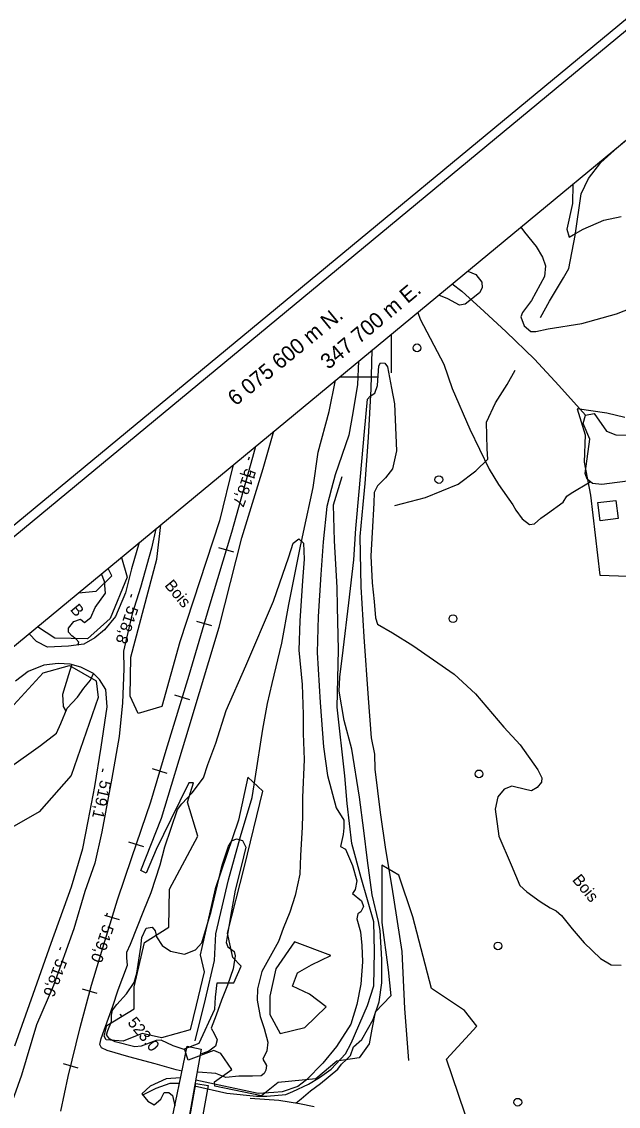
# Model space of a CAD drawing. Extents: x 347312 to 350503, y 6073086 to 6076432.
# Drawn here: x 347604 to 347759, y 6075410.5 to 6075692.2 of the extents above; entities that cross this region are included whole.
import ezdxf

# ---------------------------------------------------------------- set-up
doc = ezdxf.new("R2010")
doc.units = 0
for name, color, linetype in [('Level 1', 7, 'Continuous'), ('Level 19', 7, 'Continuous'), ('Level 2', 7, 'Continuous'), ('Level 22', 7, 'Continuous'), ('Level 23', 7, 'Continuous'), ('Level 26', 7, 'Continuous'), ('Level 3', 7, 'Continuous'), ('Level 31', 7, 'Continuous'), ('Level 36', 7, 'Continuous'), ('Level 4', 7, 'Continuous'), ('Level 44', 7, 'Continuous'), ('Level 54', 7, 'Continuous'), ('Level 60', 7, 'Continuous'), ('Level 61', 7, 'Continuous')]:
    doc.layers.add(name, color=color, linetype=linetype)

msp = doc.modelspace()

# ---------------------------------------------------------------- linework, layer by layer
at = {"layer": 'Level 1'}
for points in [[(347652.33, 6075499.3), (347654.48, 6075504.82), (347657.14, 6075513.31), (347662.23, 6075524.88), (347669.46, 6075541.69), (347673.43, 6075553.21), (347674.57, 6075556.8), (347676.01, 6075557.93), (347677.25, 6075556.76), (347677.37, 6075552.62), (347676.98, 6075547), (347676.29, 6075536.62), (347676, 6075529.02), (347676.85, 6075520.07), (347677.13, 6075512.28), (347677.18, 6075507.36), (347677.42, 6075500.6), (347676.99, 6075490.74), (347676.94, 6075486.27)], [(347616.15, 6075534.73), (347617.57, 6075536.43), (347619.25, 6075537.02), (347620.35, 6075536.19), (347621.95, 6075537.51), (347623.08, 6075540.05), (347625.8, 6075543.77), (347625.8, 6075543.77), (347625.49, 6075546.84), (347624.73, 6075548.8)], [(347618.61, 6075530.33), (347618.83, 6075531.08), (347618.16, 6075531.84), (347617.06, 6075532.67), (347616.2, 6075533.7), (347616.15, 6075534.73)], [(347615.52, 6075513.28), (347614.88, 6075514.4), (347614.66, 6075517.57), (347616.25, 6075522.63), (347617.08, 6075525.18), (347617.09, 6075525.23)], [(347645.68, 6075419.67), (347644.16, 6075420.01), (347638.69, 6075421.53), (347631.86, 6075423.39), (347626.26, 6075425.06), (347624.77, 6075425.71), (347624.34, 6075426.55), (347624.64, 6075428.14), (347627.73, 6075436.57), (347629.09, 6075440.77), (347631.47, 6075447.15), (347631.36, 6075449.07), (347631.35, 6075450.53), (347632.29, 6075452.65), (347635.71, 6075461.35), (347637.63, 6075466.02), (347639.95, 6075473.28), (347641.2, 6075477.93), (347644.49, 6075487.61), (347645.59, 6075489.05), (347648.3, 6075491.96), (347651.26, 6075495.87), (347652.33, 6075499.3)], [(347676.94, 6075486.27), (347676.92, 6075483.05), (347676.44, 6075475.69), (347676.28, 6075470.86), (347675.08, 6075465.32), (347673.7, 6075460.98), (347671.97, 6075456.73), (347670.75, 6075453.32), (347666.39, 6075445.58), (347665.3, 6075441.06), (347665.23, 6075438.06), (347665.93, 6075433.82), (347667.04, 6075430.71), (347667.96, 6075427.19), (347667.67, 6075424.94), (347666.65, 6075422.76), (347667.6, 6075421.14), (347667.41, 6075419.91), (347667.03, 6075419.06), (347666.2, 6075418.47), (347663.94, 6075418.39), (347660.46, 6075418.33), (347657.04, 6075418.05), (347654.47, 6075419.02), (347649.87, 6075419.36), (347649.59, 6075419.34)]]:
    msp.add_lwpolyline(points, dxfattribs=at)
at = {"layer": 'Level 19'}
for points in [[(347763.39, 6075573.1), (347754.7, 6075572.05), (347752.28, 6075572.24), (347750.9, 6075573.4), (347750.45, 6075574.9), (347751.65, 6075583.8), (347749.89, 6075587.88), (347750.49, 6075590), (347752.76, 6075590.44), (347755.91, 6075585.89), (347758.4, 6075584.93), (347764.31, 6075584.72)], [(347638.89, 6075560.5), (347637.75, 6075555.52), (347634.88, 6075545.23), (347632.67, 6075538.39), (347630.5, 6075528.69), (347630.54, 6075524.17), (347630.22, 6075515.32), (347629.34, 6075506.59), (347627.42, 6075495.74), (347624.86, 6075481.84), (347623, 6075473.71), (347620.39, 6075466.29), (347617.6, 6075456.6), (347612.3, 6075441.92), (347607.89, 6075431.66), (347604, 6075418.58), (347600.64, 6075409.38)], [(347634.56, 6075556.92), (347632.58, 6075550.08), (347630.99, 6075543.85), (347628.39, 6075537.73), (347625.49, 6075534.24), (347622.98, 6075532.23), (347620.13, 6075530.53), (347616.18, 6075530.01), (347610.75, 6075529.8), (347607.89, 6075531.28), (347605.93, 6075533.26)], [(347602.24, 6075426.25), (347606.96, 6075439.67), (347611.68, 6075452.92), (347616.94, 6075467.56), (347619.9, 6075477.49), (347621.31, 6075484.55), (347622.98, 6075493.59), (347624.67, 6075503.84), (347626.24, 6075514.31), (347625.87, 6075518.78), (347624.19, 6075521.35), (347622.63, 6075522.89), (347619.37, 6075524.56), (347616.62, 6075525.37), (347613.45, 6075525.53), (347609.72, 6075525.11), (347605.7, 6075523.46), (347602.42, 6075520.94)], [(347663.35, 6075412.65), (347670.82, 6075412.1), (347676.22, 6075411.29), (347680, 6075410.52)]]:
    msp.add_lwpolyline(points, dxfattribs=at)
at = {"layer": 'Level 2'}
for points in [[(347747.18, 6075649.98), (347747.08, 6075644.98), (347745.65, 6075638.32), (347746.26, 6075636.27), (347747.26, 6075636.85), (347749.89, 6075638.36), (347755.23, 6075640.63), (347759.78, 6075641.58)], [(347733.66, 6075638.81), (347734.61, 6075637.51), (347737.68, 6075633.79), (347739.32, 6075631.01), (347740.06, 6075628.83), (347739.86, 6075626), (347736.5, 6075619.76), (347734.09, 6075616.71), (347733.69, 6075615.58), (347734.56, 6075613.24), (347736.32, 6075611.76), (347737.56, 6075611.71), (347740.79, 6075612.44), (347749.56, 6075613.85), (347758.54, 6075616.35), (347764.92, 6075618.87)], [(347719.9, 6075627.44), (347721.98, 6075626.59), (347723.54, 6075624.55), (347723.69, 6075623.08), (347722.96, 6075621.82), (347719.2, 6075618.84), (347717.72, 6075618.56), (347714.74, 6075620.22), (347712.36, 6075621.21)], [(347706.92, 6075616.72), (347707.54, 6075614.94), (347713.72, 6075603.29), (347715.81, 6075596.9), (347720.42, 6075586.34), (347725.49, 6075576.03), (347727.88, 6075572.02), (347731.6, 6075566.71), (347732.42, 6075565.39)], [(347691.54, 6075604.01), (347691.27, 6075597.97), (347690.06, 6075590.6), (347689.01, 6075584.82), (347685.48, 6075574.48), (347684.49, 6075571.01), (347683.32, 6075566.33), (347682.3, 6075557.12), (347681.71, 6075548.68), (347681.04, 6075537.77), (347680.8, 6075528.42), (347681.56, 6075515.37), (347682.46, 6075503.91), (347683.45, 6075496.4), (347685.68, 6075488.06), (347687.67, 6075484.87), (347687.7, 6075482.88), (347687.54, 6075481.14), (347686.87, 6075478.04), (347688.14, 6075477.34), (347689.95, 6075473.07), (347691.12, 6075469.07), (347690.68, 6075466.83), (347689.92, 6075465.8), (347692.33, 6075463.9), (347692.78, 6075462.39), (347692.13, 6075461.05)], [(347696.7, 6075458.51), (347695.07, 6075465.49), (347693.85, 6075474.41), (347692.9, 6075482.2), (347691.8, 6075490.82), (347689.8, 6075503.26), (347687.78, 6075510.71), (347686.51, 6075518.38), (347686.63, 6075521.97), (347687.53, 6075529.01), (347689.01, 6075541.29), (347690.29, 6075552.43), (347690.85, 6075560.59), (347691.68, 6075570.18), (347693.1, 6075585.81), (347693.89, 6075594.16), (347694.57, 6075594.96), (347695.79, 6075595.72), (347696.41, 6075597.7), (347696.83, 6075602.82), (347697.26, 6075603.58), (347698.35, 6075603.54), (347699.05, 6075602.53), (347700.05, 6075596.99), (347700.84, 6075592.99), (347701.42, 6075580.72), (347700.32, 6075576.11), (347698.57, 6075573.73), (347696.41, 6075571.68), (347695.59, 6075569.95), (347695.47, 6075567.2), (347695.04, 6075559.53), (347694.68, 6075553.53), (347695.1, 6075546.44), (347695.59, 6075541.67), (347695.92, 6075537.42), (347696.49, 6075535.77), (347700.35, 6075533.51), (347705.63, 6075530.16), (347716.36, 6075522.8), (347721.92, 6075517.68), (347729.24, 6075508.98), (347733.54, 6075504.41), (347738.1, 6075497.93), (347739.14, 6075495.87), (347739.03, 6075494.72), (347737.95, 6075493.29), (347736.49, 6075492.49), (347735.27, 6075492.68), (347731.36, 6075493.71), (347729.39, 6075492.89), (347727.74, 6075490.86), (347727.01, 6075487.73), (347728.02, 6075480.72), (347731.15, 6075473.23), (347733.43, 6075467.9), (347735.23, 6075466.2), (347738.71, 6075463.75), (347741.32, 6075462.04)], [(347732.42, 6075565.39), (347734.03, 6075563.12), (347735.93, 6075561.63), (347737.26, 6075561.79), (347738.86, 6075563.24), (347740.65, 6075564.45), (347744.72, 6075567.41), (347745.68, 6075569), (347746.77, 6075569.77), (347751.7, 6075572.73)], [(347646.26, 6075425.3), (347643.33, 6075426.27), (347640.22, 6075427.72), (347638.96, 6075427.61), (347635.05, 6075426.19), (347633.42, 6075425.99), (347628.31, 6075427.25), (347626.84, 6075428.04), (347626.06, 6075429.13), (347626.39, 6075430.2), (347627.35, 6075432.6), (347627.36, 6075434.21), (347627.63, 6075435.5), (347628.72, 6075436.94), (347631.27, 6075439.71), (347633.25, 6075442.68), (347633.93, 6075445.11), (347634.94, 6075451.82), (347635.25, 6075454.35), (347636.39, 6075456.8), (347637.87, 6075457.04), (347638.66, 6075456.09), (347639.03, 6075454.53), (347640.51, 6075452.27), (347642.65, 6075450.84), (347646.27, 6075450.08), (347649.17, 6075451.13), (347650.83, 6075453.03), (347653.23, 6075461.16), (347656.07, 6075473.13), (347657.72, 6075478.1), (347658.59, 6075479.49), (347659.84, 6075479.98), (347661.4, 6075479.53), (347662.27, 6075477.85), (347661.05, 6075472.83), (347659.43, 6075466.68), (347658.26, 6075459.84), (347657.17, 6075453.05), (347657.58, 6075451.92), (347659.24, 6075450.75), (347659.5, 6075449.63), (347658.95, 6075446.24), (347657.51, 6075441.98), (347655.89, 6075438.1), (347654.55, 6075434.19), (347653.2, 6075430.8), (347654.03, 6075429.48), (347654.76, 6075427.81), (347654.38, 6075426.16), (347652.63, 6075424.85), (347650.7, 6075424.18)], [(347692.13, 6075461.05), (347691.34, 6075460.53), (347691.07, 6075459.23), (347692, 6075455.85), (347692.4, 6075452.29), (347692.52, 6075448.09), (347692.11, 6075442.25), (347691.08, 6075436.99), (347689.56, 6075431.84), (347685.82, 6075426.08), (347682.23, 6075421.77), (347678.03, 6075417.38), (347675.79, 6075415.67), (347671.67, 6075414.28), (347669.5, 6075414.1), (347665.49, 6075413.88), (347649.22, 6075417.3)], [(347741.32, 6075462.04), (347742.85, 6075461.31), (347744.27, 6075460.08), (347747, 6075456.61), (347750.15, 6075452.96), (347754.43, 6075448.9), (347757.12, 6075447.26), (347759.73, 6075447.15)], [(347675.28, 6075411.43), (347676.63, 6075412.49), (347679.02, 6075414.57), (347681.64, 6075416.47), (347686.14, 6075420.17), (347687.08, 6075421.48), (347688.41, 6075422.7), (347689.46, 6075423.72), (347690.25, 6075425.97), (347692.36, 6075427.84), (347695.3, 6075433.08), (347696.92, 6075437.64), (347697.62, 6075442.64), (347697.61, 6075448.67), (347697.14, 6075456.2), (347696.7, 6075458.51)], [(347645.31, 6075417.9), (347641.56, 6075417.68), (347637.42, 6075415.78), (347635.24, 6075413.75), (347636.81, 6075411.83), (347638.45, 6075410.9), (347640.15, 6075412.36), (347641.05, 6075414.13), (347642.2, 6075414.12), (347643.16, 6075413.36), (347643.81, 6075410.63)]]:
    msp.add_lwpolyline(points, dxfattribs=at)
at = {"layer": 'Level 22'}
for points in [[(347715.89, 6075624.13), (347718.38, 6075622.23), (347724.2, 6075616.95), (347729.9, 6075611.63), (347737.25, 6075604.56), (347743.56, 6075597.73), (347750.49, 6075590)], [(347704.6, 6075422.45), (347703.58, 6075435.93), (347702.82, 6075450.77), (347700.28, 6075467.42), (347698.63, 6075477.24), (347697.24, 6075486.83), (347695.82, 6075498.06), (347695.74, 6075502.02), (347694.86, 6075506.19), (347694.1, 6075516.55), (347692.97, 6075532.44), (347692.17, 6075545.42), (347691.99, 6075558.55), (347692.74, 6075566.82), (347693.27, 6075572.27), (347694.1, 6075584.23), (347694.82, 6075596.85), (347695.1, 6075606.95)], [(347649.12, 6075427.51), (347651.78, 6075438.36), (347654.13, 6075448.42), (347654.43, 6075455.34), (347657.77, 6075469.35), (347660.82, 6075480.62), (347663.87, 6075490.75), (347664.71, 6075495.65), (347666.62, 6075508.51), (347667.84, 6075515.17), (347669.11, 6075520.36), (347671.58, 6075530.83), (347673.44, 6075540.85), (347676.39, 6075555.6), (347677.22, 6075559.64), (347679.72, 6075571.22), (347681.07, 6075580.45), (347683.86, 6075590.99), (347685.57, 6075599.08)]]:
    msp.add_lwpolyline(points, dxfattribs=at)
at = {"layer": 'Level 23'}
for p, q in [((347664.59, 6075573.67), (347660.76, 6075574.84)), ((347659.1, 6075554.44), (347655.27, 6075555.6)), ((347653.38, 6075535.27), (347649.55, 6075536.44)), ((347647.67, 6075516.1), (347643.84, 6075517.27)), ((347641.82, 6075496.98), (347637.99, 6075498.14)), ((347635.71, 6075477.93), (347631.88, 6075479.1)), ((347629.41, 6075458.94), (347625.58, 6075460.11)), ((347623.61, 6075439.8), (347619.78, 6075440.97)), ((347618.66, 6075420.4), (347614.83, 6075421.57))]:
    msp.add_line(p, q, dxfattribs=at)
msp.add_lwpolyline([(347614.2, 6075409.25), (347616.07, 6075418.24), (347619.2, 6075431.04), (347622.12, 6075441.98), (347625.66, 6075453.7), (347628.94, 6075464.13), (347632.63, 6075475.13), (347637.59, 6075489.59), (347641.51, 6075503.06), (347647.56, 6075522.49), (347652.71, 6075540.14), (347658.57, 6075559.61), (347664.03, 6075579.1), (347664.85, 6075581.95)], dxfattribs=at)
at = {"layer": 'Level 26'}
msp.add_lwpolyline([(347642.44, 6075404.01), (347647.01, 6075426.12), (347650.68, 6075425.36), (347646.63, 6075403), (347642.44, 6075404.01)], dxfattribs=at)
at = {"layer": 'Level 3'}
for p, q in [((347663.14, 6075579.09), (347662.87, 6075578.33)), ((347632.51, 6075543.47), (347632.26, 6075542.71)), ((347625.11, 6075498.2), (347624.94, 6075497.42)), ((347626.2, 6075460.69), (347625.93, 6075459.94)), ((347614.11, 6075451.8), (347613.83, 6075451.05)), ((347629.54, 6075434.44), (347630.05, 6075433.82))]:
    msp.add_line(p, q, dxfattribs=at)
at = {"layer": 'Level 31'}
for points in [[(347754.29, 6075562.58), (347753.71, 6075567.3), (347758.39, 6075567.87), (347758.97, 6075563.16), (347754.29, 6075562.58)], [(347647.42, 6075406.13), (347649.23, 6075416.46), (347652.42, 6075415.9), (347650.59, 6075405.42), (347647.42, 6075406.13)]]:
    msp.add_lwpolyline(points, dxfattribs=at)
at = {"layer": 'Level 36'}
for centre in [(347706.72, 6075607.5), (347712.39, 6075573.29), (347716.07, 6075537.17), (347722.82, 6075496.87), (347727.76, 6075452.19), (347732.91, 6075411.6)]:
    msp.add_circle(centre, 1, dxfattribs=at)
at = {"layer": 'Level 4'}
for points in [[(347738.83, 6075615.39), (347741.15, 6075619.65), (347744.74, 6075625.7), (347746.18, 6075628.07), (347747.81, 6075636.67), (347749.37, 6075647.49), (347751.26, 6075651.47), (347754.51, 6075655.63), (347760.46, 6075660.96)], [(347700.99, 6075566.6), (347708.91, 6075568.64), (347717.38, 6075572.14), (347722.02, 6075575.53), (347725.1, 6075578.63), (347724.97, 6075581.24), (347724.77, 6075588.17), (347727.1, 6075593.2), (347730.15, 6075598.02), (347732.26, 6075601.72)], [(347648.95, 6075415.81), (347657.27, 6075413.98), (347665.04, 6075413.15), (347667.66, 6075413.21), (347672.63, 6075413.61), (347674.44, 6075414.34), (347678.5, 6075416.32), (347681.39, 6075417.98), (347684.44, 6075420.16), (347688.16, 6075424.2), (347689.63, 6075426.91), (347693.84, 6075436.71), (347695.48, 6075441.85), (347695.68, 6075450.77), (347695.54, 6075458.4), (347692.21, 6075469.91), (347689.79, 6075478.77), (347688.55, 6075489.18), (347687.97, 6075496.36), (347685.95, 6075514.17), (347686.36, 6075529.1), (347686.03, 6075540.21), (347686.01, 6075545.26), (347685.3, 6075557.34), (347685, 6075566.76), (347687.3, 6075574.1)], [(347635.45, 6075413.48), (347638.93, 6075415.26), (347642.57, 6075416.58), (347645.03, 6075416.56)]]:
    msp.add_lwpolyline(points, dxfattribs=at)
at = {"layer": 'Level 44'}
for points in [[(347760.72, 6075589.43), (347756, 6075590.52), (347748.37, 6075591.67), (347750.38, 6075584.93), (347750.17, 6075577.8), (347751.79, 6075569.22), (347754.2, 6075548.47), (347761.49, 6075548.24)], [(347650.41, 6075449.91), (347651.39, 6075445.45), (347649.3, 6075436.84), (347647.78, 6075430.37), (347640.32, 6075428.33), (347635.28, 6075429.44), (347630.35, 6075427.45), (347625.98, 6075427.77), (347625.41, 6075428.79), (347626.12, 6075431.49), (347633.26, 6075435.83), (347633.27, 6075441.59), (347635.89, 6075453.08), (347642.28, 6075457.08), (347642.42, 6075466.89), (347649.76, 6075480.65), (347647.07, 6075489.55), (347648.66, 6075494.55), (347647.44, 6075494.56), (347642.76, 6075485.05), (347638.93, 6075477.2), (347636.36, 6075471.04), (347634.95, 6075471.79), (347640.34, 6075485.4), (347647.52, 6075509.06), (347655.34, 6075534.94), (347661.18, 6075558.19), (347666.74, 6075576.15), (347669.55, 6075585.83)], [(347658.96, 6075577.08), (347655.4, 6075562.61), (347645.14, 6075531.14), (347640.41, 6075514.32), (347634.25, 6075512.5), (347632.16, 6075517.04), (347632.33, 6075527.2), (347639.14, 6075552.65), (347640.14, 6075561.53)], [(347629.9, 6075553.07), (347631.4, 6075547.93), (347627.04, 6075537.19), (347621.12, 6075531.93), (347612.66, 6075532.07), (347608.12, 6075535.07)], [(347618.76, 6075543.86), (347623.32, 6075544.31), (347627.43, 6075548.31), (347626.47, 6075550.24)], [(347597.14, 6075509.64), (347609.58, 6075523.09), (347616.39, 6075525.02), (347623.34, 6075521), (347623.85, 6075516.73), (347616.83, 6075496.42), (347608.58, 6075487.02), (347599.05, 6075481.54)], [(347720.72, 6075404.19), (347714.4, 6075422.75), (347722.28, 6075431.37), (347719.07, 6075435.44), (347710.51, 6075441.13), (347705.67, 6075459.74), (347701.97, 6075470.52), (347697.56, 6075473.19), (347697.54, 6075458.29), (347699.26, 6075445.95), (347699.91, 6075439.22), (347695.85, 6075434.96), (347694.96, 6075430.54), (347694.28, 6075426.76), (347691.7, 6075423.11), (347685.88, 6075422.26), (347680.42, 6075417.69), (347670.65, 6075416.71), (347666.32, 6075413.28), (347654.19, 6075415.73), (347654.11, 6075416.88), (347658.58, 6075420.13), (347655.79, 6075424.24), (347653.89, 6075425.03), (347647.29, 6075422.51), (347646.28, 6075425.43), (347650.13, 6075426.93), (347654.18, 6075435.73), (347654.33, 6075438.88), (347654.76, 6075442.58), (347659.15, 6075442.58), (347661.01, 6075446.91), (347658.89, 6075449.18), (347657.49, 6075455.54), (347661.91, 6075472.84), (347666.66, 6075492.39), (347662.78, 6075496.02), (347660.34, 6075484.82), (347654.25, 6075467), (347650.41, 6075449.91)], [(347671.2, 6075429.44), (347677.58, 6075431), (347683.11, 6075436.38), (347678.78, 6075439.63), (347674.37, 6075441.75), (347675.68, 6075445.16), (347679.33, 6075447.25), (347684.32, 6075449.73), (347674.88, 6075453.28), (347670.05, 6075446.23), (347668.48, 6075439.1), (347668.46, 6075434.38), (347671.2, 6075429.44)]]:
    msp.add_lwpolyline(points, dxfattribs=at)
at = {"layer": 'Level 54'}
msp.add_lwpolyline([(347600.77, 6075498.41), (347608.88, 6075504.27), (347613.05, 6075507.41), (347614.17, 6075509.97), (347615.8, 6075513.95), (347618.49, 6075516.8), (347620.17, 6075519.16), (347621.9, 6075521.18), (347622.63, 6075522.89)], dxfattribs=at)
at = {"layer": 'Level 60'}
for p, q in [((347700, 6075611), (347700, 6075601)), ((347686.69, 6075600), (347696.69, 6075600))]:
    msp.add_line(p, q, dxfattribs=at)
msp.add_lwpolyline([(348655.35, 6076431.86), (347312.14, 6075321.93)], dxfattribs=at)
for points in [[(349159.76, 6073089.49), (347315.28, 6075321.63), (348655.04, 6076428.72), (350499.52, 6074196.58)], [(348779.44, 6073584.28), (350085.28, 6074663.34), (348652.09, 6076397.74), (347346.25, 6075318.68)]]:
    msp.add_lwpolyline(points, close=True, dxfattribs=at)

# ---------------------------------------------------------------- texts
at = {"layer": 'Level 3'}
for s, rotation, p in [('518,7', 250.5613, (347662.14, 6075576.38)), ('518,8', 251.3759, (347631.56, 6075540.75)), ('519,1', 257.5244, (347624.45, 6075495.4)), ('519,0', 250.6998, (347625.21, 6075457.98)), ('518,6', 249.3627, (347613.07, 6075449.12)), ('523,0', 309.5679, (347631.35, 6075432.2))]:
    msp.add_text(s, height=3, rotation=rotation, dxfattribs=at).set_placement(p)
at = {"layer": 'Level 44'}
for s, p in [('Bois', (347640.98, 6075545.76)), ('B', (347616.46, 6075539.48)), ('Bois', (347746.9, 6075469.27))]:
    msp.add_text(s, height=3, rotation=309.568, dxfattribs=at).set_placement(p)
at = {"layer": 'Level 61'}
for s, rotation, p in [('347 700 m E. ', 39.813, (347683.7, 6075601.71)), ('6 075 600 m N.', 39.3644, (347659.59, 6075592.25))]:
    msp.add_text(s, height=4, rotation=rotation, dxfattribs=at).set_placement(p)

doc.saveas('drawing.dxf')
